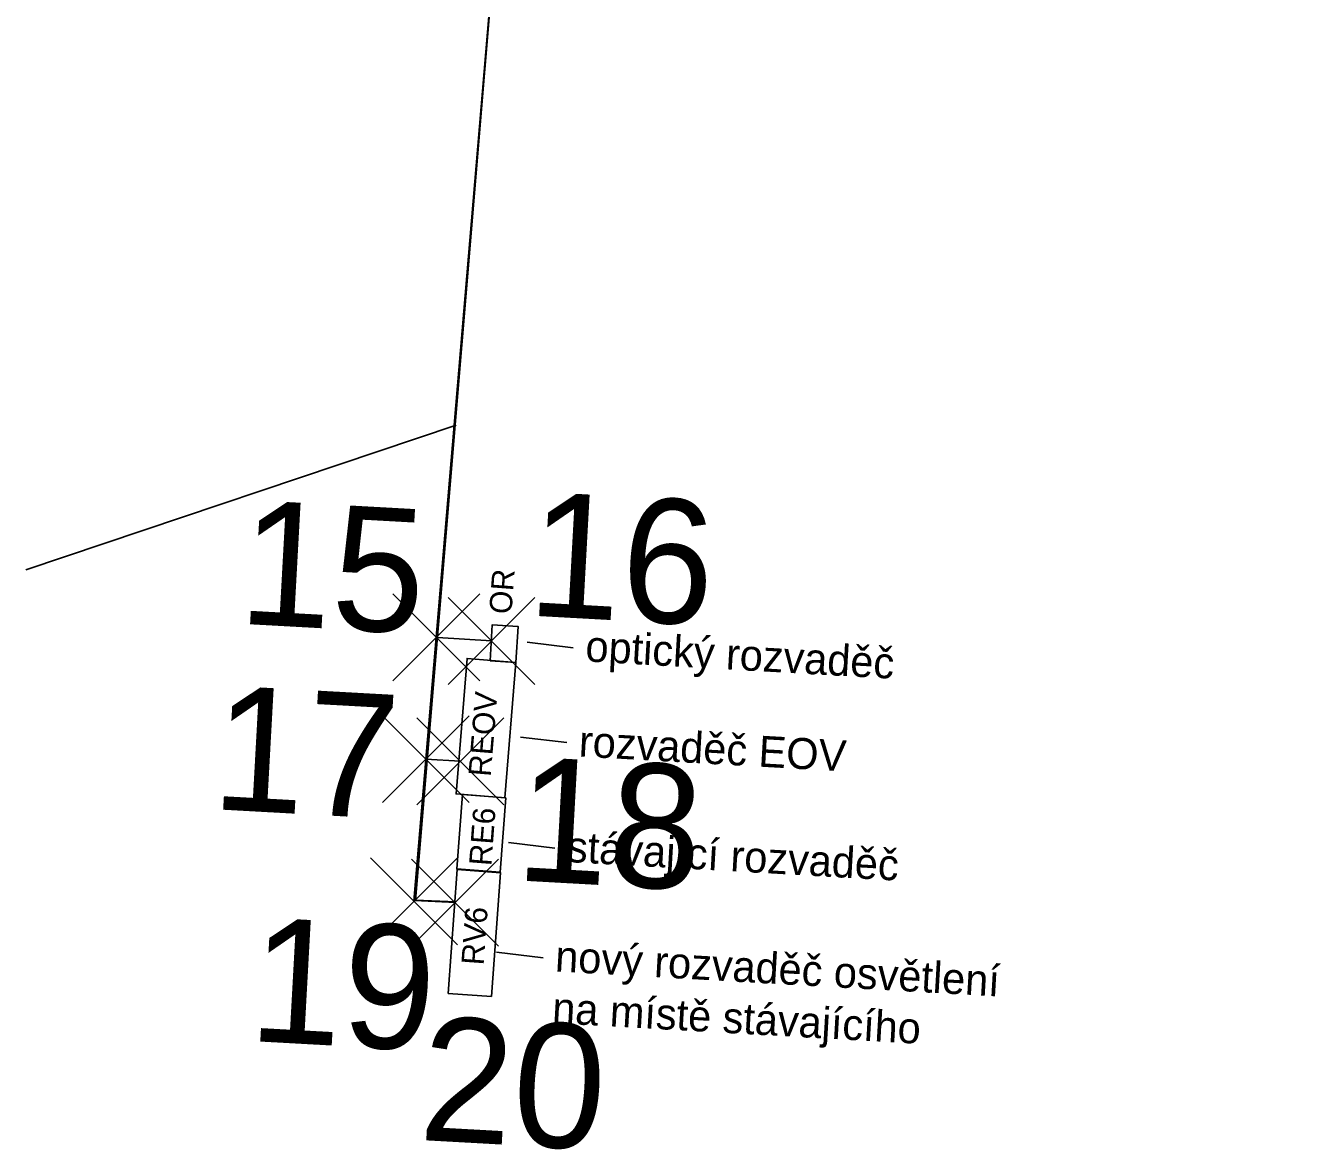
# Model space of a CAD drawing. Extents: x -669661 to -669105, y -977202 to -977030.
# Drawn here: x -669521.65 to -669511.31, y -977157.71 to -977148.65 of the extents above; entities that cross this region are included whole.
import ezdxf

# ---------------------------------------------------------------- set-up
doc = ezdxf.new("R2010")
doc.units = 0
for name, color, linetype in [('elektro-EOV', 7, 'Continuous'), ('elektro-osvetleni', 7, 'Continuous'), ('Elektro-VO+EOV', 7, 'Continuous'), ('SO 01-86-01_vytyč_body', 7, 'Continuous')]:
    doc.layers.add(name, color=color, linetype=linetype)

# ---------------------------------------------------------------- blocks, each defined once
blk = doc.blocks.new('POINT_DISPLAY')
for p, q in [((-0.35, -0.35), (0.35, 0.35)), ((-0.35, 0.35), (0.35, -0.35))]:
    blk.add_line(p, q)

msp = doc.modelspace()

# ---------------------------------------------------------------- linework, layer by layer
at = {"layer": 'elektro-EOV'}
for p, q in [((-669518.18, -977151.872), (-669521.648, -977153.038)), ((-669517.609, -977153.619), (-669517.236, -977153.664)), ((-669517.662, -977154.384), (-669517.289, -977154.429)), ((-669517.758, -977155.235), (-669517.385, -977155.28)), ((-669517.822, -977155.478), (-669518.171, -977155.452)), ((-669517.895, -977156.475), (-669517.822, -977155.478)), ((-669518.515, -977155.7), (-669518.186, -977155.718)), ((-669517.854, -977156.117), (-669517.48, -977156.162))]:
    msp.add_line(p, q, dxfattribs=at)
msp.add_lwpolyline([(-669445.341, -977152.857), (-669517.763, -977146.78), (-669518.507, -977155.699), (-669518.183, -977155.713)], dxfattribs=at)
for points in [[(-669517.787, -977154.874), (-669517.698, -977153.783), (-669518.092, -977153.75), (-669518.181, -977154.842)], [(-669517.895, -977156.475), (-669517.822, -977155.478), (-669518.171, -977155.452), (-669518.244, -977156.45)]]:
    msp.add_lwpolyline(points, close=True, dxfattribs=at)
at = {"layer": 'elektro-osvetleni'}
msp.add_lwpolyline([(-669445.341, -977152.857), (-669517.763, -977146.78), (-669518.52, -977155.707)], dxfattribs=at)
msp.add_lwpolyline([(-669517.826, -977155.473), (-669517.78, -977154.875), (-669518.129, -977154.848), (-669518.175, -977155.447)], close=True, dxfattribs=at)
at = {"layer": 'Elektro-VO+EOV'}
msp.add_line((-669517.895, -977153.61), (-669518.331, -977153.581), dxfattribs=at)
msp.add_lwpolyline([(-669376.446, -977151.556), (-669386.675, -977150.085), (-669402.797, -977150.85), (-669412.108, -977150.726), (-669421.416, -977150.84), (-669436.037, -977150.686), (-669443.348, -977150.615), (-669443.485, -977152.976), (-669517.763, -977146.78), (-669518.424, -977154.562), (-669518.147, -977154.579)], dxfattribs=at)
msp.add_lwpolyline([(-669517.906, -977153.771), (-669517.698, -977153.783), (-669517.681, -977153.493), (-669517.89, -977153.481)], close=True, dxfattribs=at)

# ---------------------------------------------------------------- block references
at = {"layer": 'SO 01-86-01_vytyč_body'}
for p in [(-669518.34, -977153.581), (-669517.895, -977153.61), (-669518.424, -977154.562), (-669518.147, -977154.579), (-669518.52, -977155.707), (-669518.19, -977155.718)]:
    msp.add_blockref('POINT_DISPLAY', p, dxfattribs=at)

# ---------------------------------------------------------------- texts
at = {"layer": 'elektro-EOV'}
msp.add_text('REOV', height=0.18, rotation=85.3123, dxfattribs=at).set_placement((-669517.902, -977154.707))
at = {"layer": 'elektro-osvetleni'}
for s, height, rotation, p in [('optický rozvaděč', 0.25, 356.761, (-669517.143, -977153.774)), ('rozvaděč EOV', 0.25, 356.761, (-669517.196, -977154.54)), ('RE6', 0.18, 85.6742, (-669517.897, -977155.426)), ('stávající rozvaděč', 0.25, 356.761, (-669517.292, -977155.39)), ('RV6', 0.18, 85.8169, (-669517.959, -977156.226)), ('nový rozvaděč osvětlení ', 0.25, 356.761, (-669517.387, -977156.272)), ('na místě stávajícího', 0.25, 356.761, (-669517.411, -977156.688))]:
    msp.add_text(s, height=height, rotation=rotation, dxfattribs=at).set_placement(p)
at = {"layer": 'Elektro-VO+EOV'}
msp.add_text('OR', height=0.18, rotation=85.6742, dxfattribs=at).set_placement((-669517.735, -977153.398))
at = {"layer": 'SO 01-86-01_vytyč_body'}
for s, p in [('15', (-669519.942, -977153.47)), ('16', (-669517.613, -977153.404)), ('17', (-669520.159, -977154.964)), ('18', (-669517.712, -977155.538)), ('19', (-669519.86, -977156.832)), ('20', (-669518.488, -977157.63))]:
    msp.add_text(s, height=1, rotation=356.8465, dxfattribs=at).set_placement(p)

doc.saveas('drawing.dxf')
